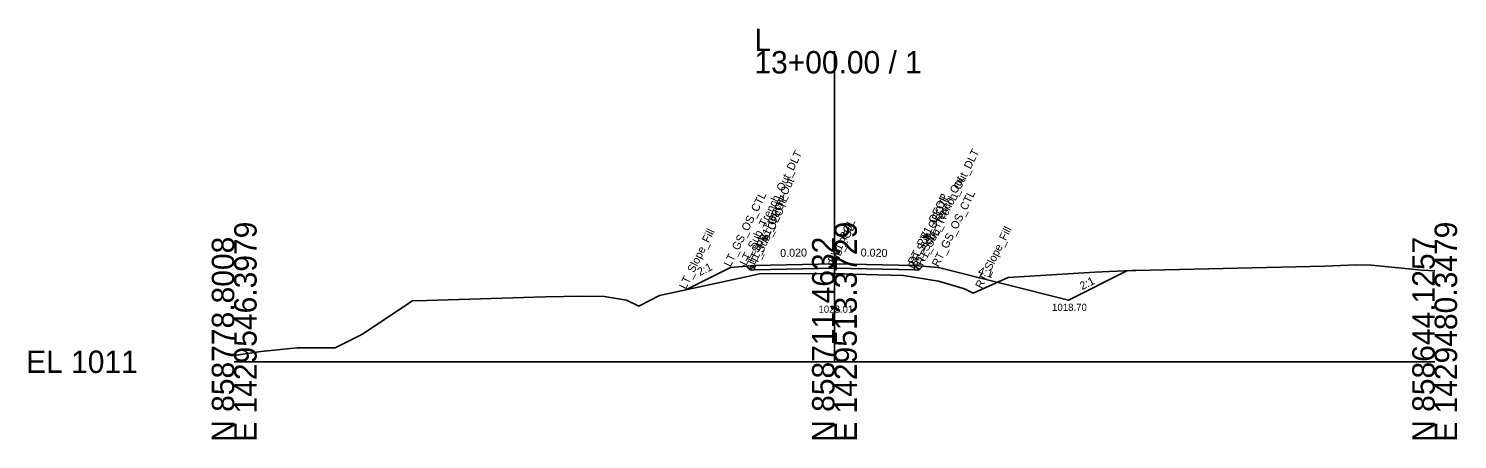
# Model space of a CAD drawing. Extents: x -26 to 153, y -10 to 13058.
# Drawn here: x -25.7 to 152.8, y 2990.3 to 3041.6 of the extents above; entities that cross this region are included whole.
import ezdxf

# ---------------------------------------------------------------- set-up
doc = ezdxf.new("R2010")
doc.units = 0
for name, color, linetype in [('Default', 7, 'Continuous'), ('Exist Cross Section Cell', 7, 'Continuous'), ('Exist XS Center Line Elevation Label', 7, 'Continuous'), ('Exist XS Ground Line', 7, 'Continuous'), ('Prop CMT Pvmt Course 1', 7, 'Continuous'), ('Prop CMT Pvmt Surface', 7, 'Continuous'), ('Prop CMT Pvmt Surface Shoulder', 7, 'Continuous'), ('Prop CMT Shld Paved Course 1', 7, 'Continuous'), ('Prop CMT Slope Grass', 7, 'Continuous'), ('Prop CMT Subgrade Earthwork', 7, 'Continuous'), ('Prop XS Dump Level', 7, 'Continuous'), ('Prop XS SE Text', 7, 'Continuous'), ('Prop XS Side Slope Text', 7, 'Continuous')]:
    doc.layers.add(name, color=color, linetype=linetype)

msp = doc.modelspace()

# ---------------------------------------------------------------- linework, layer by layer
at = {"layer": 'Exist Cross Section Cell'}
for p, q in [((75, 3000), (75, 3038.78)), ((0, 3000), (75, 3000)), ((75, 3000), (150, 3000))]:
    msp.add_line(p, q, dxfattribs=at)
at = {"layer": 'Exist XS Ground Line'}
msp.add_lwpolyline([(0, 3000.79), (3.33, 3001.29), (7.86, 3001.73), (9.04, 3001.75), (12.6, 3001.73), (15.96, 3003.38), (22.29, 3007.62), (24.06, 3007.64), (36.14, 3008), (38.85, 3008.12), (43.5, 3008.2), (46.25, 3008.14), (49.01, 3007.67), (50.56, 3006.95), (53.14, 3008.26), (64.33, 3010.69), (65.28, 3010.9), (65.63, 3010.97), (74.66, 3011.02), (75, 3011.01), (77.34, 3010.94), (83.63, 3010.75), (87.99, 3010.07), (91.26, 3009.09), (92.35, 3008.57), (96.72, 3010.5), (107.55, 3011.17), (112.16, 3011.38), (112.65, 3011.38), (136.29, 3011.93), (140.2, 3012.1), (142.11, 3012.04), (148.38, 3011.42), (150, 3011.33)], dxfattribs=at)
at = {"layer": 'Prop CMT Pvmt Course 1'}
for points in [[(75, 3012.2), (65, 3012)], [(65, 3012), (65, 3011.46)], [(75, 3011.66), (75, 3012.2)], [(75, 3012.2), (85, 3012)], [(75, 3011.66), (75, 3012.2)], [(85, 3012), (85, 3011.46)], [(65, 3011.46), (75, 3011.66)], [(85, 3011.46), (75, 3011.66)]]:
    msp.add_lwpolyline(points, dxfattribs=at)
at = {"layer": 'Prop CMT Pvmt Surface'}
for points in [[(75, 3012.2), (65, 3012)], [(75, 3012.2), (85, 3012)]]:
    msp.add_lwpolyline(points, dxfattribs=at)
at = {"layer": 'Prop CMT Pvmt Surface Shoulder'}
for points in [[(65, 3012), (65, 3012)], [(85, 3012), (85, 3012)]]:
    msp.add_lwpolyline(points, dxfattribs=at)
at = {"layer": 'Prop CMT Shld Paved Course 1'}
for points in [[(65, 3012), (64.45, 3011.45)], [(65, 3012), (65, 3012)], [(65, 3011.46), (65, 3012)], [(85, 3012), (85, 3012)], [(85, 3012), (85.55, 3011.45)], [(85, 3011.46), (85, 3012)], [(64.45, 3011.45), (65, 3011.46)], [(85.55, 3011.45), (85, 3011.46)]]:
    msp.add_lwpolyline(points, dxfattribs=at)
at = {"layer": 'Prop CMT Slope Grass'}
for p, q in [((88, 3011.76), (104.24, 3007.7)), ((104.24, 3007.7), (111.53, 3011.35))]:
    msp.add_line(p, q, dxfattribs=at)
for points in [[(65, 3012), (62, 3011.76), (56.42, 3008.97)], [(85, 3012), (88, 3011.76), (88, 3011.76)]]:
    msp.add_lwpolyline(points, dxfattribs=at)
at = {"layer": 'Prop CMT Subgrade Earthwork'}
for points in [[(64.45, 3011.45), (63.98, 3011.92)], [(85.55, 3011.45), (86.02, 3011.92)], [(65, 3011.46), (64.45, 3011.45)], [(75, 3011.66), (65, 3011.46)], [(75, 3011.66), (85, 3011.46)], [(85, 3011.46), (85.55, 3011.45)]]:
    msp.add_lwpolyline(points, dxfattribs=at)

# ---------------------------------------------------------------- texts
at = {"layer": 'Default'}
for s, height, p in [('1018.70', 0.9, (102.19, 3006.34)), ('-', 0.0001, (0, 3000))]:
    msp.add_text(s, height=height, dxfattribs=at).set_placement(p)
at = {"layer": 'Exist Cross Section Cell'}
for s, p in [('L', (65, 3038.78)), ('13+00.00 / 1', (65, 3035.98)), ('EL 1011', (-26, 2998.6))]:
    msp.add_text(s, height=2.8, dxfattribs=at).set_placement(p)
for s, p in [('E 1429546.3979', (2.8, 2990)), ('E 1429513.3729', (77.8, 2990)), ('E 1429480.3479', (152.8, 2990)), ('N 858778.8008', (0, 2990)), ('N 858711.4632', (75, 2990)), ('N 858644.1257', (150, 2990))]:
    msp.add_text(s, height=2.8, rotation=90, dxfattribs=at).set_placement(p)
at = {"layer": 'Exist XS Center Line Elevation Label'}
msp.add_text('1022.01', height=0.9, dxfattribs=at).set_placement((73, 3006.11))
msp.add_text('1022.01', height=0.9, dxfattribs=at).set_placement((73, 3006.11))
msp.add_text('1022.01', height=0.9, dxfattribs=at).set_placement((73, 3006.11))
at = {"layer": 'Prop XS Dump Level'}
for s, p in [('LT_Sub_Trench_Out_DLT', (63.98, 3011.92)), ('RT_Sub_Trench_Out_DLT', (86.02, 3011.92)), ('RT_Sub_Trench_Out_DLT', (86.02, 3011.92)), ('LT_Sub_Trench_Out', (64.45, 3011.45)), ('RT_Sub_Trench_Out', (85.55, 3011.45)), ('RT_Sub_Trench_Out', (85.55, 3011.45)), ('LT_GS_OS_CTL', (62, 3011.76)), ('LT_GS_OS_CTL', (62, 3011.76)), ('LT_PV1_OEOT', (65, 3012)), ('RT_PV1_OEOT', (85, 3012)), ('RT_PV1_OEOT', (85, 3012)), ('RT_PS1_OEOP', (85, 3012)), ('RT_PS1_OEOP', (85, 3012)), ('RT_GS_OS_CTL', (88, 3011.76)), ('RT_GS_OS_CTL', (88, 3011.76)), ('LT_PS1_OEOP', (65, 3012)), ('LT_Sub_OEOT', (65, 3011.46)), ('RT_Sub_OEOT', (85, 3011.46)), ('RT_Sub_OEOT', (85, 3011.46)), ('PV1_PGL', (75, 3012.2)), ('LT_Slope_Fill', (56.42, 3008.97)), ('LT_Slope_Fill', (56.42, 3008.97)), ('Sub_PGL', (75, 3011.66)), ('RT_Slope_Fill', (93.43, 3009.05))]:
    msp.add_text(s, height=1, rotation=63.5833, dxfattribs=at).set_placement(p)
at = {"layer": 'Prop XS SE Text'}
for rotation, p in [(1.1458, (68.23, 3013.07)), (358.8542, (78.27, 3013.14))]:
    msp.add_text('0.020', height=1, rotation=rotation, dxfattribs=at).set_placement(p)
at = {"layer": 'Prop XS Side Slope Text'}
for s, rotation, p in [('2:1', 26.5651, (58.17, 3010.68)), ('4:1', 345.9638, (92.88, 3010.91)), ('2:1', 26.5651, (105.95, 3008.93))]:
    msp.add_text(s, height=1, rotation=rotation, dxfattribs=at).set_placement(p)

doc.saveas('drawing.dxf')
